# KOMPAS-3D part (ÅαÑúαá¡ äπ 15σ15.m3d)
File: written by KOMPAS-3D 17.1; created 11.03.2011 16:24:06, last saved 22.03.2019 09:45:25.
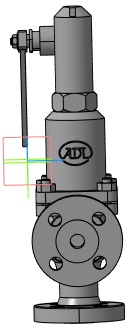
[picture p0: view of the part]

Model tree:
1. Плоскость XY
2. Плоскость ZX
3. Плоскость ZY
4. Ось X
5. Ось Y
6. Ось Z
7. Начало координат
8. Операция без истории:2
